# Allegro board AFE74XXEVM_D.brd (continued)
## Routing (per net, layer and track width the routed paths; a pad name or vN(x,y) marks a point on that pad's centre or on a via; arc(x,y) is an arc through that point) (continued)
VDDA_1.0V: length 1.6
  L4_SIG w0.203: 53.75,66.95 53.6,67.1 v1(53.55,67.1) 53.54,67.1 53.26,66.83 ; 53.77,60.1 53.58,59.9 v1(53.55,59.9) 53.51,59.9 53.26,60.15
  BOTTOM w0.102: 54.69,59.28 54.69,59.33 54.58,59.44 54.53,59.44
  vias: v1(54.83,47.46) v1(54.83,46.58) v1(54.83,45.69) v1(55.63,48.33) v1(55.85,47.46) v1(55.85,46.58) v1(55.85,45.69) v1(104.65,17.02) v1(104.65,16) v1(104.65,14.99) v1(104.65,13.84) v1(105.92,17.02) v1(105.92,16) v1(105.92,14.99) v1(105.92,13.84)
VDDA_1.8V: length 0.2
  BOTTOM w0.305: v1(51.15,66.3) 51.06,66.3 C79.1 ; v1(51.15,61.5) 51.14,61.49 C80.1
  vias: v1(31.24,67.7) v1(31.17,54.86) v1(31.91,67.7) v1(31.85,54.84) v1(33.91,78.96) v1(34.47,78.6) v1(36,44.61) v1(36.53,44.93) v1(38.03,71.19) v1(38.03,68.38) v1(37.95,58.45) v1(37.97,55.78) v1(37.96,52.88) v1(38.1,73.91) v1(39.98,65.13) v1(40.11,51.1) v1(40.21,76.09) v1(41.45,48.74) v1(41.61,78.47) v1(51.15,65.5) v1(51.15,60.7) v1(86.28,32.56) v1(86.28,31.55) v1(87.3,32.56) v1(87.3,31.55) v1(88.32,32.56) v1(88.32,31.55) v1(89.33,32.56) v1(89.33,31.55) v3(37.54,55.12) v3(37.57,59.09) v3(37.67,71.76) v3(37.67,67.8) v3(38.33,59.09) v3(38.25,55.12) v3(38.42,71.78) v3(38.39,67.81) v3(39.5,51.49) v3(39.58,75.77) v3(40.11,51.84) v3(40.24,75.39) v3(41.45,48.01) v3(41.6,79.21) v3(42.06,48.36) v3(42.26,78.83)
VDDA_SERDES_1.0V: length 1.1
  L8_PWR_SIG w0.102: 61.98,58.52 61.82,58.68 61.39,58.68 61.31,58.6 61.14,58.6
  BOTTOM w0.254: v1(63.15,68.7) C115.1 ; C116.1 v1(63.15,58.3)
  vias: v1(62.35,68.7) v1(62.35,58.3) v1(74.93,75.36) v1(136.58,36.45) v1(136.6,35.56) v1(137.59,36.47) v1(137.62,35.59) v1(138.71,36.47) v1(138.73,35.59) v1(139.6,36.47) v1(139.62,35.59)
VDDCLK_1.0V: length 1.8
  BOTTOM w0.305: 52.75,61.43 C109.1 ; 52.75,61.43 v1(52.75,61.5) ; 52.75,61.43 v1(52.75,60.7) ; v1(51.95,63.1) 51.94,63.09 C431.1 ; v1(52.75,66.3) v1(52.75,65.5)
  vias: v1(61.76,45.19) v1(104.65,12.19) v1(104.65,11.18) v1(104.65,10.16) v1(104.65,9.14) v1(105.79,12.19) v1(105.79,11.18) v1(105.79,10.16) v1(105.79,9.14)
VDDE: length 5.1
  L8_PWR_SIG w0.305: v1(54.35,64.7) v1(54.35,65.5) v1(54.35,66.3) v1(54.35,67.1) ; v1(54.35,62.3) v1(54.35,61.5) v1(54.35,60.7) v1(54.35,59.9)
  BOTTOM w0.305: C123.1 54.43,67.18 v1(54.35,67.1)
  vias: v1(68.11,50.3) v1(133.63,15.9) v1(133.63,13.84) v1(133.65,14.96) v1(134.75,15.88) v1(134.77,14.94) v1(134.75,13.82) v3(62.36,55.24) v3(63.41,53.06) v3(63.9,53.54)
VDDGPIO_1.8V: length 309.8
  TOP w0.508: J9.60 J9.63
  L3_PWR w0.102: 51.66,58.47 51.52,58.47 51.31,58.68 50.99,58.68 50.73,58.42 50.73,58.22
  L3_PWR w0.381: 51.74,58.12 51.92,58.3 v1(51.95,58.3)
  L3_PWR w0.508: 165.07,110.39 165.07,101.36 165.05,101.34 165.05,95.31 165.07,95.28 165.07,85.5 180.92,69.65 180.92,64.69 181.15,64.47 181.15,50.33 181.76,49.72 181.76,48.91 180.96,48.11 180.96,47.39 181.48,46.87 181.48,46.35 180.59,45.46 180.59,44.59 180.9,44.29 180.9,43.57 179.91,42.58 179.91,42.05 180.94,41.02 180.94,38.9 180.2,38.16 180.2,36.26 180.57,35.89 180.57,33.48 179.15,32.05 173.66,32.05 172.54,30.94 169.32,30.94 167.97,32.28 163.37,32.28 157.23,26.14 157.23,19.41 152.68,14.86 144.25,14.86 142.21,12.83 138.33,12.83 133.07,7.56 132.32,7.56 131.59,6.84 131.59,6.09 129.01,3.51 124.74,3.51 121.79,6.45 116.97,6.45 113.85,3.33 99.77,3.33 92.81,10.29 92.81,16.23 93.45,16.87 93.45,20.94 93.32,21.06 93.32,22.96 93.45,23.08 93.45,25.04 93.34,25.14 93.34,27.38 93.52,27.56 v1(93.52,31.55) ; 165.07,110.39 J9.60 ; 165.07,110.39 J9.57 162.41,111.76 156.77,111.76 155.35,113.18 155.35,118.87 154.05,120.17 JP7.2 ; JP7.2 154.99,122.38 v1(155.88,122.38) 155.88,122.33 156.79,121.41 159.13,121.41 JP8.2 ; JP7.2 152.3,121.56 149.45,121.56 v1(148.64,122.38) 147.75,122.38 JP6.2 144.86,121.36 142.44,121.36 141.55,122.25 v1(141.55,122.28) 140.74,122.28 JP5.2 137.9,121.51 134.98,121.51 v1(134.16,122.33) 133.45,122.33 JP4.2 130.38,121.23 127.79,121.23 126.87,122.15 v1(126.87,122.2) 126.21,122.2 JP3.2 123.29,121.51 120.5,121.51 v1(119.66,122.35) ; v1(112.55,122.35) 113.59,121.31 115.85,121.31 117.86,123.32 118.82,122.35 v1(119.66,122.35) ; v1(119.41,118.01) 119.66,118.26 v1(119.66,122.35)
  vias: v1(49.99,54.89) v1(90.47,32.56) v1(90.47,31.55) v1(91.49,32.56) v1(91.49,31.55) v1(92.51,32.56) v1(92.51,31.55) v1(93.52,32.56)
VDDL1_1.0V: length 4
  L8_PWR_SIG w0.102: 52.59,60.32 52.68,60.32 ; 52.59,60.32 52.59,60.28 52.37,60.06 52.37,59.67 52.55,59.49 ; 52.59,60.32 52.37,60.54 52.37,60.86 52.63,61.12 52.63,61.14
  BOTTOM w0.305: v1(53.55,61.5) v1(53.55,60.7) ; C106.1 53.39,66.46 v1(53.55,66.3) v1(53.55,65.5)
  vias: v1(55.96,54.33) v1(107.04,22.61) v1(107.04,21.59) v1(107.04,20.57) v1(107.04,19.56) v1(108.31,22.61) v1(108.31,21.59) v1(108.31,20.57) v1(108.31,19.56)
VDDL2_1.0V: length 3.9
  L8_PWR_SIG w0.102: 50.51,67.52 50.19,67.52 49.97,67.74 49.97,68.14 49.91,68.2 ; 50.8,67.36 50.8,67.29 50.77,67.26 50.77,66.94 50.99,66.72 51.33,66.72 51.38,66.78 ; 51.77,68.28 52.11,68.28 52.33,68.06 52.33,67.74 52.32,67.73 52.32,67.67
  BOTTOM w0.305: C103.1 51.79,61.66 v1(51.95,61.5) ; C102.1 51.77,65.32 v1(51.95,65.5)
  vias: v1(41.85,73.38) v1(51.95,66.3) v1(51.95,60.7) v1(104.39,7.37) v1(104.39,6.35) v1(104.39,5.33) v1(104.39,4.32) v1(105.66,7.37) v1(105.66,6.35) v1(105.66,5.33) v1(105.66,4.32)
VDDPLL_1.0V: length 5.6
  L8_PWR_SIG w0.102: 49.28,65.15 49.35,65.08 49.71,65.08 49.93,64.86 49.93,64.41 ; 50.73,63.71 50.73,64.06 50.51,64.28 50.19,64.28 50.15,64.24 50.14,64.24
  L8_PWR_SIG w0.127: 38.4,58.57 38.4,58.27 38.02,57.89 37.85,57.89 ; 43.51,62.81 43.65,62.67 43.65,62.66 43.91,62.4 44.81,62.4 45.21,62.79
  BOTTOM w0.305: v1(51.15,63.1) 50.96,62.91 C92.1
  vias: v1(45.29,65.05) v1(94.74,23.75) v1(94.74,22.61) v1(94.74,21.59) v1(94.74,20.57) v1(96.01,23.75) v1(96.01,22.61) v1(96.01,21.59) v1(96.01,20.57)
VDDPLL_1.8V: length 0.9
  L3_PWR w0.102: 50.72,62.2 50.72,62.05 50.55,61.88 50.34,61.88
  BOTTOM w0.305: v1(51.15,63.9) 50.98,64.07 C94.1
  vias: v1(43.61,48.87) v1(77.65,32.56) v1(77.65,31.55) v1(78.66,32.56) v1(78.66,31.55) v1(79.81,32.56) v1(79.81,31.55) v1(80.82,32.56) v1(80.82,31.55)
VDDR_SERDES_1.5V: length 4.1
  L8_PWR_SIG w0.102: 64.31,60.93 64.25,60.93 64.11,61.08 63.79,61.08 63.65,60.93 63.5,60.93 63.49,60.92 ; 62.03,60.93 62.05,60.93 62.19,61.08 62.51,61.08 62.77,60.82 62.77,60.86 62.99,61.08 63.33,61.08 63.49,60.92 ; 63.58,60.83 63.49,60.92 ; 64.33,60.83 64.59,61.08 64.91,61.08 65.05,60.93 65.15,60.93
  L8_PWR_SIG w0.127: 65.18,60.93 65.15,60.93
  BOTTOM w0.305: v1(63.15,59.9) 63.24,59.9 C112.1 ; v1(63.15,67.1) 63.24,67.1 C113.1
  vias: v1(62.35,67.1) v1(62.35,59.9) v1(68.88,56.64) v1(122.89,35.2) v1(122.89,34.19) v1(123.98,35.23) v1(123.98,34.21) v1(125.04,35.23) v1(125.04,34.21) v1(126.09,35.26) v1(126.09,34.24)
VDDT_SERDES_1.0V: length 0.2
  BOTTOM w0.305: C118.1 63.23,65.5 v1(63.15,65.5) ; C119.1 v1(63.15,61.5)
  vias: v1(62.35,65.5) v1(62.35,61.5) v1(131.65,36.5) v1(131.65,35.56) v1(132.69,36.5) v1(132.69,35.56) v1(133.78,36.5) v1(133.78,35.56) v1(134.77,36.5) v1(134.77,35.56)
VDDTX_1.0V: length 1.3
  L3_PWR w0.102: 56.11,55.52 55.79,55.52 55.57,55.74 55.57,56.04 55.5,56.11
  BOTTOM w0.305: C100.1 53.64,62.39 v1(53.55,62.3)
  vias: v1(58.37,55.27) v1(62.76,51.82) v1(105.28,31.37) v1(105.28,30.35) v1(105.28,29.34) v1(105.28,28.32) v1(106.43,31.37) v1(106.43,30.35) v1(106.43,29.34) v1(106.43,28.32)
VDDTX_1.8V: length 4.9
  L8_PWR_SIG w0.102: 51.56,61.57 51.53,61.54 51.53,61.34 51.3,61.11 51.05,61.11 ; 51.64,62.81 51.64,62.87 51.57,62.94 51.57,63.26 51.79,63.48 51.89,63.48 ; 51.87,61.88 52.07,61.88 52.33,62.14 52.33,62.31 ; 50.83,62.03 50.83,62.09 50.77,62.14 50.77,62.46 50.99,62.68 51.39,62.68 51.54,62.53 ; 50.31,60.32 50.51,60.32 50.73,60.54 50.73,60.74 50.77,60.78 50.77,60.83
  BOTTOM w0.305: v1(52.75,63.1) 52.74,63.09 C98.1
  vias: v1(43.91,57.53) v1(82.09,32.56) v1(82.09,31.55) v1(83.11,32.56) v1(83.11,31.55) v1(84.12,32.56) v1(84.12,31.55) v1(85.14,32.56) v1(85.14,31.55)
VDDVCO_1.8V: length 5.7
  L8_PWR_SIG w0.102: 51.44,65.15 51.53,65.25 51.53,65.66 51.31,65.88 50.96,65.88 50.93,65.91 ; 50.19,66.7 50.21,66.68 50.51,66.68 50.73,66.46 50.73,66.14 50.69,66.1 ; 49.28,67.44 49.35,67.44 49.39,67.48 49.71,67.48 49.93,67.26 49.93,66.94
  L8_PWR_SIG w0.127: 37.41,68.66 37.68,68.66 37.85,68.83 38.49,68.83 38.66,68.66
  BOTTOM w0.254: v1(51.95,63.9) 52.1,64.05 C96.1 52.1,64.55 v1(51.95,64.7)
  vias: v1(46.84,68.1) v1(95.05,32.56) v1(95.05,31.42) v1(96.06,32.56) v1(96.06,31.42) v1(97.08,32.56) v1(97.08,31.42) v1(98.09,32.56) v1(98.09,31.42)
VEE: length 0.3
  BOTTOM w0.305: C64.1 51.09,67.9 v1(51.15,67.9) ; v1(51.95,67.9) 52.04,67.9 C62.1
  vias: v1(32.16,36.36) v1(49.81,72.42) v1(51.15,59.1) v1(51.15,58.3) v1(51.95,68.7) v1(51.95,59.1) v1(79.43,6.32) v1(79.4,5.36) v1(80.54,6.32) v1(80.52,5.36) v1(81.74,5.36) v1(81.76,6.32) v1(82.88,6.3) v1(82.85,5.33) v3(49.02,68.68) v3(49.02,67.94) v3(48.97,59.05) v3(48.97,58.34)
3P3V_FMC:
  vias: v2(211.46,43.81) v2(211.46,41.27) v2(211.46,38.73) v2(212.73,40)
3P3VAUX:
  vias: v1(187.2,20.17) v1(187.87,20.17) v1(188.52,20.17) v2(211.46,48.89)
A_IN1: length 15.1
  TOP w0.381: J14.1 29.09,15.62 arc(30.5,17.37) 32.41,18.56 R50.2 38.83,21.17 R54.1
A_IN2: length 15.3
  TOP w0.381: R332.1 R330.2 43.09,12.38 arc(42.51,10.18) 41.56,8.11 J15.1
ADC_ALT_SYNC_N: length 167.1
  L6_SIG w0.102: v2(206.38,48.89) 205.94,49.33 203.52,49.33 203.5,49.31 203.48,49.31 ; v1(57.55,65.5) 57.14,65.09 56.56,65.09 56.34,64.87 56.34,64.38 56.24,64.28 55.79,64.28 55.57,64.06 55.57,63.32 55.53,63.28 55.53,55.36
  L6_SIG w0.127: 55.53,55.36 55.53,55.28 55.75,55.06 56.35,55.06 57.95,53.45 58.67,53.45 63.35,48.77 63.35,48.54 63.93,47.96 66.93,47.96 67.84,48.87 100.23,48.87 101.02,48.08 201.73,48.08 202.96,49.31 203.48,49.31
ADC_ALT_SYNC_P: length 167.1
  L6_SIG w0.102: v1(56.75,65.5) 56.75,65.54 57.12,65.91 57.68,65.91 57.68,65.91 57.72,65.91 57.96,65.67 57.96,65.63 57.96,65.63 57.96,64.57 57.71,64.32 57.41,64.32 57.17,64.08 57.17,63.78 56.91,63.52 56.61,63.52 56.36,63.27 56.36,55.65 56.65,55.36 ; v2(206.38,50.16) 205.94,49.73 203.67,49.73 203.66,49.75 203.48,49.75
  L6_SIG w0.127: 203.48,49.75 202.78,49.75 201.55,48.51 101.2,48.51 100.41,49.3 67.66,49.3 66.75,48.39 64.11,48.39 63.78,48.72 63.78,48.95 58.85,53.88 58.13,53.88 56.65,55.36
ADC_SYNC_N: length 158.6
  L6_SIG w0.102: v2(207.65,73.02) 207.21,73.46 206.97,73.46 205.7,72.19 203.48,72.19 ; v1(57.55,61.5) 57.97,61.92 58.51,61.92 58.73,62.14 58.73,62.53 58.92,62.72 59.31,62.72 59.57,62.98 59.57,65.66 59.79,65.88 59.79,65.89 64.88,65.89 65.08,66.09 65.15,66.09
  L6_SIG w0.127: 65.15,66.09 65.58,66.09 65.69,65.98 65.69,65.89 65.8,65.78 65.96,65.78 66.07,65.89 66.07,65.98 66.18,66.09 66.34,66.09 66.45,65.98 66.45,65.89 66.56,65.78 66.72,65.78 66.83,65.89 66.83,65.98 66.94,66.09 67.1,66.09 67.21,65.98 67.21,65.89 67.32,65.78 67.48,65.78 67.59,65.89 67.59,65.98 67.7,66.09 67.86,66.09 67.97,65.98 67.97,65.89 68.08,65.78 68.24,65.78 68.35,65.89 68.35,65.98 68.47,66.09 73.05,66.09 73.2,65.94 104.52,65.94 110.67,72.09 201.37,72.09 201.47,72.19 203.48,72.19
ADC_SYNC_P: length 158.6
  L6_SIG w0.102: v1(56.75,61.5) 57.13,61.88 57.13,62.5 57.35,62.72 57.76,62.72 57.97,62.93 57.97,63.26 58.19,63.48 58.51,63.48 58.77,63.74 58.77,66.46 58.99,66.68 64.91,66.68 65.07,66.52 65.15,66.52 ; 203.48,72.62 203.49,72.62 203.5,72.61 203.65,72.61 203.67,72.59 205.51,72.59 206.78,73.86 207.21,73.86 v2(207.65,74.3)
  L6_SIG w0.127: 203.48,72.62 201.29,72.62 201.19,72.52 110.49,72.52 104.34,66.37 73.38,66.37 73.23,66.52 65.15,66.52
AIN1: length 3.9
  TOP w0.381: C132.2 L7.2 40.5,27.39 T4.3
AIN1M: length 10
  TOP w0.203: C136.1 46.99,48.03 arc(47.04,48.26) 47.16,48.45 47.46,48.77 48.78,50 arc(49.2,50.41) 49.59,50.86 49.77,51.07 arc(50.83,52.53) 51.73,54.08 52.21,55.02 52.21,55.02 52.31,55.22 arc(52.35,55.29) 52.39,55.36 arc(52.39,55.36) 52.4,55.36 arc(52.57,55.63) 52.75,55.89 U1.A16
AIN1P: length 10
  TOP w0.203: U1.A17 51.95,55.9 arc(52.08,55.74) 52.09,55.53 51.83,55.01 51.44,54.23 arc(50.56,52.71) 49.51,51.28 49.34,51.07 arc(48.96,50.64) 48.56,50.24 46.98,48.79 arc(46.85,48.64) 46.75,48.47 46.63,48.19 arc(46.56,48.1) 46.45,48.07 C131.1
AIN2: length 3.9
  TOP w0.381: T6.3 L51.2 C471.2
AIN2M: length 10
  TOP w0.203: U1.A13 55.04,55.84 55,55.71 54.96,55.54 54.96,55.54 54.93,55.41 54.93,55.41 54.93,55.37 54.92,55.36 54.92,55.36 54.59,53.82 54.59,53.81 54.55,53.5 arc(54.2,51.45) 53.58,49.47 52.44,46.59 C475.1
AIN2P: length 10
  TOP w0.203: C474.1 52.12,46.67 53.27,49.59 arc(53.88,51.53) 54.23,53.54 54.26,53.87 54.27,53.89 54.6,55.43 54.6,55.54 arc(54.58,55.64) 54.52,55.73 U1.A14
ALARM_TX1: length 1.6
  BOTTOM w0.127: J7.1 125.55,94.26 Q3.1
ALARM_TX2: length 1.6
  BOTTOM w0.127: Q4.1 128.09,94.26 J7.4
ALARMTX1: length 124.1
  L4_SIG w0.102: 49.15,58.71 51.28,58.71 51.56,58.43 51.56,57.89 v1(51.95,57.5)
  L4_SIG w0.127: J7.2 123.62,98.32 122.68,97.38 v1(120.68,97.38) ; v1(50.32,97) 47.3,93.99 47.3,88.56 46.19,87.45 46.19,85.05 48.42,82.83 48.42,78.82 48.07,78.47 48.07,76.6 48.52,76.15 48.52,75.78 48.12,75.38 48.12,67.93 48.4,67.65 48.4,62.11 47.76,61.47 47.76,60.41 48.63,59.54 48.63,58.91 48.83,58.71 49.15,58.71
  L8_PWR_SIG w0.127: v1(120.68,97.38) 120.47,97.18 118.41,97.18 117.81,97.79 108.64,97.79 107.67,96.82 105.84,96.82 105.59,97.08 98.18,97.08 97.67,97.59 90.12,97.59 89.84,97.3 83.31,97.3 83.1,97.1 67.83,97.1 67.6,97.32 60.33,97.32 59.39,96.39 57.69,96.39 56.69,97.38 50.7,97.38 v1(50.32,97)
ALARMTX2: length 111
  L4_SIG w0.102: v1(51.95,69.5) 51.91,69.5 51.56,69.85 51.56,71.5
  L4_SIG w0.127: 51.56,71.5 51.56,71.53 51.95,71.92 51.95,72.94 51.66,73.23 51.66,78.97 52.96,80.27 52.96,80.3 53.27,80.61 53.27,87.22 51.78,88.72 51.78,93.4 55.35,96.97 v1(55.35,98.48)
  L6_SIG w0.127: v1(120.21,98.84) 120.21,97.22 120.5,96.93 126.7,96.93 J7.5
  L8_PWR_SIG w0.127: v1(55.35,98.48) 56.75,98.48 57.79,99.52 60.88,99.52 61.8,98.6 67.37,98.6 67.5,98.73 67.51,98.73 67.8,99.02 68.34,99.57 68.74,99.57 69.36,98.95 72.92,98.95 73.38,98.48 89.09,98.48 89.61,99.01 98.17,99.01 98.78,98.4 105.56,98.4 107.68,100.52 113.6,100.52 114.35,99.77 119.28,99.77 v1(120.21,98.84)
B_IN1: length 19
  TOP w0.381: J16.1 59.85,5 arc(60.05,7.02) 60.62,8.96 R72.2 R76.1
B_IN2: length 20
  TOP w0.381: J17.1 73.81,4.27 arc(73.67,6.48) 73.27,8.66 R335.2 R337.1
BIN1: length 4
  TOP w0.381: C137.2 L8.2 63.11,25.55 62.35,28.4 T8.3
BIN1M: length 9.7
  TOP w0.203: C145.1 58.33,46.51 arc(58.19,46.57) 58.13,46.7 57.38,55.35 57.38,55.42 57.37,55.5 arc(57.41,55.72) U1.A10
BIN1P: length 9.7
  TOP w0.203: C144.1 57.81,46.57 57.05,55.32 57.05,55.39 57.05,55.42 57.04,55.42 arc(56.95,55.7) 56.75,55.9 U1.A11
BIN2: length 4
  TOP w0.381: T10.3 67.88,29.88 68.64,27.04 L55.2 C479.2
BIN2M: length 9.7
  TOP w0.203: C483.1 63.73,48.05 arc(63.68,48.2) 63.64,48.35 63.49,48.89 63.22,49.51 63.21,49.53 arc(62.84,49.99) 62.39,50.38 61.07,51.34 arc(60.5,51.9) 60.1,52.59 arc(59.98,53.04) 59.91,53.51 59.79,55.36 59.79,55.37 59.79,55.63 59.75,55.66 arc(59.75,55.67) 59.75,55.68 arc(59.79,55.82) 59.91,55.89 U1.A7
BIN2P: length 9.7
  TOP w0.203: C482.1 63.37,47.87 63.37,48.04 63.32,48.27 63.18,48.78 62.93,49.35 62.93,49.35 arc(62.6,49.77) 62.2,50.12 60.88,51.07 arc(60.23,51.7) 59.79,52.47 59.79,52.47 arc(59.65,52.97) 59.58,53.48 59.46,55.33 59.46,55.36 59.42,55.62 arc(59.42,55.62) 59.42,55.63 arc(59.42,55.64) 59.42,55.66 arc(59.34,55.81) 59.19,55.89 U1.A8
BOOT: length 1.3
  TOP w0.305: R235.2 154.21,13.2 U16.4
C_IN1: length 15.4
  TOP w0.381: R94.1 R96.2 31.16,110.86 arc(30.37,111.42) 29.77,112.19 J18.1
C_IN2: length 15.5
  TOP w0.381: R342.1 R340.2 43.9,115.52 arc(43.24,117.61) 42.29,119.57 J19.1
CAR_SYSREF_M: length 3
  BOTTOM w0.203: U3.4 104.59,85.91 104.67,85.83 104.67,85.4 104.32,85.05 104.32,84.28 R162.1 104.19,84.1 R158.1
CAR_SYSREF_P: length 3.1
  BOTTOM w0.203: U3.3 105.09,85.89 105,85.8 105,85.27 104.65,84.91 104.65,84.3 R163.1 104.83,83.52 R156.1
CAR_SYSREFM: length 108.7
  BOTTOM w0.102: 203.48,77.32 203.5,77.32 203.56,77.37 207.54,77.37 207.65,77.27 J32.G10
  BOTTOM w0.203: R158.2 104.33,82.74 104.33,81.18 107.1,78.41 144.3,78.41 144.75,78.87 146.66,78.87 147.12,78.41 153.9,78.41 154.38,78.89 156.24,78.89 156.72,78.41 159.33,78.41 159.72,78.79 161.65,78.79 162.03,78.41 164.24,78.41 164.77,78.94 165.94,78.94 166.47,78.41 201.44,78.41 202.53,77.32 203.48,77.32
CAR_SYSREFP: length 108.7
  BOTTOM w0.102: 203.48,77.65 203.5,77.65 203.56,77.6 207.56,77.6 207.65,77.69 J32.G9
  BOTTOM w0.203: R156.2 104.66,82.74 104.66,81.32 105.02,80.96 105.27,80.96 105.36,81.05 105.62,81.05 105.79,80.87 105.79,80.62 105.7,80.53 105.7,80.28 107.24,78.74 144.16,78.74 144.62,79.2 146.8,79.2 147.25,78.74 153.76,78.74 154.24,79.22 156.37,79.22 156.85,78.74 159.2,78.74 159.58,79.12 161.78,79.12 162.16,78.74 164.1,78.74 164.63,79.27 166.08,79.27 166.61,78.74 201.57,78.74 202.67,77.65 203.48,77.65
CIN1: length 3.9
  TOP w0.381: C155.2 L12.2 T12.3
CIN1M: length 10
  TOP w0.203: U1.Y16 52.61,71.2 52.56,71.5 52.46,71.79 52.44,71.85 47.16,78.86 C147.1
CIN1P: length 10
  TOP w0.203: U1.Y17 52.18,71.33 52.18,71.6 52.14,71.69 46.61,79.04 C146.1
CIN2: length 3.9
  TOP w0.381: C487.2 L59.2 T14.3
CIN2M: length 10
  TOP w0.203: C491.1 52.57,80.51 54.96,71.58 54.96,71.58 54.99,71.5 U1.Y13
CIN2P: length 10
  TOP w0.203: U1.Y14 54.54,71.23 54.6,71.5 54.62,71.58 52.26,80.4 C490.1
CLK0_M2C_N: length 143.5
  L6_SIG w0.102: v2(206.38,83.19) 206.38,83.5 206.49,83.61 206.8,83.61 207.13,83.94 207.21,84.02 207.21,88.65
  L6_SIG w0.127: 207.21,88.65 207.21,88.73 207.19,88.75 207.19,88.82 206.2,89.81 205.84,89.81 193.11,89.81 192.58,89.28 191.34,89.28 190.8,89.81 180.65,89.81 175.18,95.28 175.18,96.78 173.38,98.58 170.54,98.58 169.33,99.78 114.79,99.78 112.62,97.61 107.82,97.61 105.97,95.76 105.97,87.66 104.52,86.21 102.31,86.21 101.72,85.61 100.9,85.61 99.84,86.67 93.92,86.67 92.48,88.11 92.48,89.01 92.58,89.11 92.58,89.42 92.48,89.52 92.48,91.75 92.9,92.17 93.48,92.17 v1(93.59,92.06)
CLK0_M2C_P: length 143.4
  L6_SIG w0.102: v2(206.38,84.45) 206.38,84.12 206.49,84.01 206.63,84.01 206.72,84.11 206.81,84.19 206.81,88.56 206.75,88.61 206.75,88.65
  L6_SIG w0.127: 206.75,88.65 206.02,89.38 193.29,89.38 192.76,88.85 191.16,88.85 190.63,89.38 180.47,89.38 174.75,95.1 174.75,96.6 173.2,98.15 170.36,98.15 169.15,99.35 114.97,99.35 112.8,97.18 108,97.18 106.4,95.58 106.4,87.48 104.7,85.78 102.49,85.78 101.9,85.18 100.72,85.18 99.66,86.24 93.74,86.24 92.05,87.93 92.05,91.97 92.68,92.6 93.53,92.6 v1(93.59,92.67)
CLK1_M2C_N: length 143.3
  L6_SIG w0.102: 208.5,88.65 208.5,88.63 208.48,88.62 208.48,87.82 208.73,87.58 208.73,86.5 208.39,86.16 207.75,86.16 207.65,86.06 v2(207.65,85.72)
  L6_SIG w0.127: 208.5,88.65 208.5,90.08 206.12,92.46 200.99,92.46 199.14,94.31 199.14,99.42 197.33,101.22 189.89,101.22 189.6,100.93 188.56,100.93 187.55,101.93 186.16,101.93 185.39,101.17 185.39,99.7 185.06,99.36 183.97,99.36 182.63,100.71 177.7,100.71 176.81,99.82 171.88,99.82 168.85,102.86 141,102.86 140.44,102.3 128.21,102.3 128.12,102.39 116.45,102.39 116.11,102.72 115.02,102.72 114.68,102.39 100.61,102.39 99.8,101.57 97.03,101.57 94.77,99.31 92.56,99.31 91.74,98.5 91.74,97.46 92.11,97.09 92.11,96.08 91.82,95.79 91.82,94.64 92.43,94.03 93.73,94.03 93.84,93.93 v1(94.26,93.93)
CLK1_M2C_P: length 143.3
  L6_SIG w0.102: v2(207.65,86.99) 207.65,86.66 207.75,86.56 208.22,86.56 208.32,86.66 208.32,87.41 208.08,87.66 208.08,88.45 208.06,88.47 208.06,88.65
  L6_SIG w0.127: v1(94.26,94.56) 93.84,94.56 93.73,94.46 92.61,94.46 92.25,94.82 92.25,95.61 92.54,95.9 92.54,96.17 92.66,96.28 92.88,96.28 92.99,96.39 92.99,96.55 92.88,96.66 92.66,96.66 92.54,96.77 92.54,97.27 92.18,97.64 92.18,98.32 92.74,98.88 92.89,98.88 93,98.77 93,98.56 93.11,98.45 93.27,98.45 93.38,98.56 93.38,98.77 93.49,98.88 94.95,98.88 97.21,101.14 99.97,101.14 100.79,101.96 114.86,101.96 115.19,102.29 115.94,102.29 116.27,101.96 127.94,101.96 128.03,101.87 140.62,101.87 141.18,102.43 168.67,102.43 171.7,99.39 176.99,99.39 177.88,100.28 182.45,100.28 183.79,98.93 185.24,98.93 185.83,99.52 185.83,100.99 186.33,101.5 187.38,101.5 188.38,100.5 189.78,100.5 190.07,100.79 197.15,100.79 198.7,99.24 198.7,98.79 198.59,98.68 198.33,98.68 198.22,98.57 198.22,98.41 198.33,98.3 198.59,98.3 198.7,98.19 198.7,94.13 200.81,92.02 205.94,92.02 206.15,91.81 206.15,91.66 206.03,91.53 206.03,91.38 206.14,91.27 206.3,91.27 206.42,91.39 206.58,91.39 208.06,89.9 208.06,89.75 207.95,89.63 207.86,89.63 207.75,89.52 207.75,89.36 207.86,89.25 207.95,89.25 208.06,89.14 208.06,88.65
CLK-IN: length 3.7
  BOTTOM w0.381: R161.2 97.96,108.01 R165.1 97.93,106.02 T24.6 R159.1
CLK_LAO_0M: length 110.6
  L6_SIG w0.102: 203.48,81.08 203.49,81.08 207.42,81.08 207.65,80.85 v2(207.65,80.64)
  L6_SIG w0.127: 203.48,81.08 203.36,81.2 176.69,81.2 174.99,82.91 173.17,82.91 171.34,81.08 169.15,81.08 167.32,82.91 165.49,82.91 163.67,81.08 161.48,81.08 159.65,82.91 157.82,82.91 156,81.08 153.81,81.08 151.98,82.91 150.15,82.91 148.32,81.08 146.14,81.08 144.31,82.91 142.48,82.91 140.65,81.08 138.47,81.08 136.64,82.91 134.81,82.91 132.98,81.08 130.8,81.08 128.97,82.91 127.14,82.91 125.39,81.15 123.7,81.15 117.68,87.17 112.6,87.17 112.09,87.68 110.72,87.68 v1(110.62,87.58)
CLK_LAO_0P: length 110.7
  L6_SIG w0.102: 203.48,81.64 203.5,81.64 203.66,81.48 207.47,81.48 207.65,81.66 v2(207.65,81.91)
  L6_SIG w0.127: v1(110.62,88.19) 110.69,88.11 112.27,88.11 112.78,87.6 117.86,87.6 123.88,81.58 125.21,81.58 126.96,83.34 129.15,83.34 130.98,81.51 132.8,81.51 134.63,83.34 136.82,83.34 138.65,81.51 140.47,81.51 142.3,83.34 144.49,83.34 146.32,81.51 148.15,81.51 149.97,83.34 152.16,83.34 153.99,81.51 155.82,81.51 157.64,83.34 159.83,83.34 161.66,81.51 163.49,81.51 165.32,83.34 167.5,83.34 169.33,81.51 171.16,81.51 172.99,83.34 175.17,83.34 176.87,81.64 203.48,81.64
CLK_N: length 13.1
  L6_SIG w0.102: 49.15,64.05 49.33,64.05 49.36,64.02 49.43,64.02 49.75,63.7 50.15,63.7 v1(50.35,63.9)
  L6_SIG w0.127: v1(39.24,62.81) 39.51,62.55 40.16,62.55 41.66,64.05 49.15,64.05
  BOTTOM w0.305: R295.1 50.23,63.78 v1(50.35,63.9)
  BOTTOM w0.381: R323.1 39.17,62.74 v1(39.24,62.81) L2.1
CLK_P: length 13.1
  L6_SIG w0.102: 49.15,63.61 49.26,63.61 49.58,63.3 50.15,63.3 v1(50.35,63.1)
  L6_SIG w0.127: 49.15,63.61 41.84,63.61 40.34,62.12 39.43,62.12 v1(39.24,61.93)
  BOTTOM w0.305: v1(50.35,63.1) 50.28,63.17 R295.2
  BOTTOM w0.381: R322.1 39.17,62.03 L1.1 v1(39.24,61.93)
CLKIN1_N: length 1.4
  BOTTOM w0.381: L43.2 99.66,98.41 99.66,98.97 C230.2 99.59,99.03 C231.2
CLKIN1_P: length 0.8
  BOTTOM w0.381: L44.2 98.98,98.48 C227.2
CLKIN1N: length 2.1
  BOTTOM w0.203: L43.1 99.48,97.04 99.48,96.76 C239.2 99.54,96.55 99.54,95.48 U3.35
CLKIN1P: length 2.1
  BOTTOM w0.203: L44.1 99.09,97.04 99.09,96.76 C238.2 99.14,96.44 99.14,95.49 U3.34
CLKINN: length 2.9
  BOTTOM w0.381: C231.1 99.59,100.86 R166.2 100.43,101.7 T24.3
CLKINP: length 4.4
  BOTTOM w0.381: C227.1 98.96,99.67 R157.1 98.96,100.84 R166.1 97.89,101.9 T24.1 R159.2
CLKLA_0M: length 3.2
  BOTTOM w0.203: U3.63 107.74,87.6 107.82,87.69 108.5,87.69 108.53,87.72 109.21,87.72 R192.1 109.98,87.55 R191.1
CLKLA_0P: length 3.2
  BOTTOM w0.203: U3.62 107.74,88.1 107.82,88.02 108.37,88.02 108.4,88.05 109.21,88.05 R190.1 109.98,88.21 R189.1
CLKN: length 94.7
  L6_SIG w0.127: v1(96.78,82.4) 96.57,82.4 96.27,82.1 96.27,80.59 95.67,79.98 93.37,79.98 93.07,79.68 93.07,75.21 92.15,74.3 84.87,74.3 80.47,78.69 79.72,78.69 79.22,79.19 79.22,83.96 78.95,84.23 78.58,84.23 78.37,84.02 73.78,84.02 73.49,83.73 73.49,81.95 71.51,79.96 68.42,79.96 67.16,81.23 67.16,82.01 65.66,83.51 63.9,83.51 62.46,82.07 59.65,82.07 58.41,80.83 56.78,80.83 54.82,78.87 52.74,78.87 51.83,77.97 51.83,77.31 52.3,76.84 52.3,74.9 51.49,74.09 48.56,74.09 46.41,71.94 44.95,71.94 42.62,69.6 42.62,67.34 41.71,66.43 38.87,66.43 38.39,65.95 38.39,65.79 38.49,65.7 38.49,65.54 38.38,65.43 38.22,65.43 38.12,65.52 37.96,65.52 37.72,65.28 37.72,63.84 37.83,63.73 38.04,63.73 38.15,63.61 38.15,63.46 38.04,63.34 37.83,63.34 37.72,63.23 37.72,62.92 38.03,62.61 38.3,62.61 39.27,63.58 v1(39.27,63.83)
CLKP: length 94.7
  L6_SIG w0.127: v1(39.27,60.91) 39.27,61.21 38.3,62.18 37.85,62.18 37.29,62.74 37.29,65.46 38.69,66.86 41.53,66.86 42.19,67.52 42.19,69.78 44.78,72.37 46.23,72.37 48.39,74.52 51.31,74.52 51.87,75.08 51.87,76.66 51.4,77.13 51.4,78.15 52.56,79.31 54.64,79.31 56.6,81.26 58.23,81.26 59.47,82.5 62.28,82.5 63.72,83.94 65.84,83.94 67.59,82.19 67.59,81.41 68.6,80.39 71.33,80.39 73.06,82.12 73.06,83.91 73.6,84.45 78.19,84.45 78.4,84.66 79.13,84.66 79.65,84.14 79.65,79.37 79.9,79.12 80.65,79.12 85.05,74.73 91.97,74.73 92.64,75.39 92.64,79.86 93.19,80.41 95.49,80.41 95.84,80.76 95.84,82.28 96.33,82.77 v1(96.33,82.85)
CNTR_TAP_CHA: length 7.1
  BOTTOM w0.381: v1(35.04,46.55) L29.2 C188.2 C187.1 ; v1(35.04,46.55) C190.1 C191.1 C187.1 ; v1(35.04,46.55) C187.1
CNTR_TAP_CHB: length 7.2
  BOTTOM w0.381: C199.1 v1(31.38,57.1) ; C199.1 C200.2 C194.1 31.38,58.03 v1(31.38,57.1) ; C199.1 30.3,56.21 ; v1(31.38,57.1) 31.38,56.2 ; C193.1 31.37,56.21 31.38,56.2 ; 31.38,56.2 L31.2
CNTR_TAP_CHC: length 7
  BOTTOM w0.381: v1(35.12,80.67) C206.1 ; v1(35.12,80.67) C209.1 C207.2 34.17,81.28 C206.1 ; v1(35.12,80.67) 34.77,80.06 L37.2 33.77,80.48 33.73,80.47 C206.1
CNTR_TAP_CHD: length 6.9
  BOTTOM w0.381: C218.1 C213.1 C212.1 v1(31.38,69.81) ; C218.1 C219.2 L39.2 v1(31.38,69.81) ; C218.1 v1(31.38,69.81)
CP1: length 31.8
  TOP w0.305: C222.1 97.46,94.56 v3(97.41,94.61) ; C222.1 98.04,94.56 v3(98.09,94.61) ; C222.1 96.82,94.62 95.81,95.63 95.81,101.88 94.46,103.23 94.46,106.48 101.63,113.64 106.76,113.64 v1(107.43,112.97) 107.89,112.51 v1(107.94,112.51)
  BOTTOM w0.305: U3.32 97.42,94.61 v3(97.41,94.61)
CP2: length 2.6
  TOP w0.254: C226.1 C225.1 106.27,94.77 105.41,94.77 v3(105.08,95.1)
D_IN1: length 19.5
  TOP w0.381: J20.1 60.82,123.67 arc(61.06,121.05) 61.81,118.52 R118.2 R115.1
D_IN2: length 20.2
  TOP w0.381: R347.1 R345.2 73.84,115.56 arc(74.55,120.22) 74.8,124.94 J21.1
DAC_ALT_SYNC_N: length 169.1
  L6_SIG w0.102: v2(208.92,64.14) 208.92,64.41 208.76,64.57 208.17,64.57 207.7,65.04 207.7,65.8 208.08,66.18 208.08,74.47 207.82,74.73 203.53,74.73 203.5,74.7 203.48,74.7 ; 65.15,68.33 64.97,68.33 64.96,68.32 58.23,68.32 57.97,68.06 57.97,66.99 57.93,66.95 57.93,66.94 57.55,66.56 v1(57.55,66.3)
  L6_SIG w0.127: 65.15,68.33 65.63,68.33 65.7,68.4 66.09,68.4 66.2,68.29 66.2,68.26 66.31,68.15 66.47,68.15 66.58,68.26 66.58,68.29 66.69,68.4 66.85,68.4 66.96,68.29 66.96,68.26 67.07,68.15 67.23,68.15 67.34,68.26 67.34,68.29 67.45,68.4 67.61,68.4 67.72,68.29 67.72,68.26 67.84,68.15 67.99,68.15 68.11,68.26 68.11,68.29 68.22,68.4 68.37,68.4 68.49,68.29 68.49,68.26 68.6,68.15 68.76,68.15 68.87,68.26 68.87,68.29 68.98,68.4 69.14,68.4 69.25,68.29 69.25,68.26 69.36,68.15 69.52,68.15 69.63,68.26 69.63,68.29 69.74,68.4 69.9,68.4 70.01,68.29 70.01,68.26 70.12,68.15 70.28,68.15 70.39,68.26 70.39,68.29 70.5,68.4 70.66,68.4 70.77,68.29 70.77,68.26 70.88,68.15 71.04,68.15 71.15,68.26 71.15,68.29 71.26,68.4 71.6,68.4 72.16,68.96 103.89,68.96 111,76.07 201.42,76.07 202.79,74.7 203.48,74.7
DAC_ALT_SYNC_P: length 169.1
  L6_SIG w0.102: 203.48,75.13 207.99,75.13 208.48,74.64 208.48,66.01 208.1,65.63 208.1,65.21 208.34,64.97 208.76,64.97 208.92,65.13 v2(208.92,65.41) ; 65.15,68.91 65.13,68.91 64.93,69.12 57.43,69.12 57.17,68.86 57.17,66.75 56.75,66.34 v1(56.75,66.3)
  L6_SIG w0.127: 65.15,68.91 65.63,68.91 65.7,68.83 71.42,68.83 71.98,69.39 103.71,69.39 110.82,76.5 201.6,76.5 202.97,75.13 203.48,75.13
DAC_SYNC_N: length 176.2
  L6_SIG w0.102: v1(57.55,60.7) 57.97,61.12 63.29,61.12 63.53,60.88 63.53,58.98 63.83,58.68 64.91,58.68 65.12,58.47 65.15,58.47 ; v2(208.92,75.56) 209.35,76 210.36,76 210.62,75.74 210.62,67.28 210.53,67.19 210.24,67.19 210.15,67.11 210.15,66.98 210.24,66.89 210.53,66.89 210.62,66.8 210.62,63.87 210.45,63.7 206.96,63.7 206.87,63.79 206.87,64.05 206.78,64.14 206.66,64.14 206.57,64.05 206.57,63.79 206.48,63.7 204.27,63.7 204.04,63.93 203.48,63.93
  L6_SIG w0.127: 65.15,58.47 66.43,58.47 66.8,58.1 66.95,58.1 66.99,58.14 67.15,58.14 67.26,58.02 67.26,57.87 67.22,57.83 67.22,57.68 68.7,56.2 72.25,56.2 73.31,57.25 76.58,57.25 77.6,58.27 77.6,59.06 78.87,60.32 192.94,60.32 193.05,60.44 193.05,60.56 193.16,60.67 193.32,60.67 193.43,60.56 193.43,60.44 193.55,60.32 195.86,60.32 198.91,63.37 201.88,63.37 202.44,63.93 203.48,63.93
DAC_SYNC_P: length 176.2
  L6_SIG w0.102: 203.48,63.5 203.64,63.5 203.67,63.53 203.88,63.53 204.1,63.3 210.62,63.3 211.02,63.7 211.02,75.91 210.53,76.4 209.35,76.4 v2(208.92,76.83) ; v1(56.75,60.7) 57.17,60.28 57.39,60.28 57.39,60.28 62.51,60.28 62.77,60.02 62.77,58.14 63.02,57.89 64.88,57.89 65.03,58.04 65.15,58.04
  L6_SIG w0.127: 65.15,58.04 66.25,58.04 68.52,55.77 72.43,55.77 73.48,56.82 76.76,56.82 78.03,58.09 78.03,58.88 79.05,59.89 196.04,59.89 199.09,62.94 202.06,62.94 202.62,63.5 203.48,63.5
DACCLK_IN: length 18.8
  BOTTOM w0.381: C4.1 16.97,62.88 arc(15.95,62.67) 15.08,62.1 10.85,57.86 arc(8.68,56.41) 6.12,55.91 J1.1
DACOUT: length 109.3
  TOP w0.127: R321.2 156.69,28.86 147.02,38.53 84.79,38.53 84.23,37.97 82.65,37.97 67.95,52.68 R21.2
DCLKOUT4N: length 4.4
  BOTTOM w0.203: C254.1 93.62,90.8 R188.1 94.4,90.64 94.98,90.64 95.36,91.02 97.19,91.02 97.28,91.11 U3.25
DCLKOUT4P: length 4.4
  BOTTOM w0.203: C253.1 93.62,90.14 R187.1 94.4,90.31 95.12,90.31 95.5,90.69 97.24,90.69 97.33,90.61 U3.24
DCLKOUT6N: length 3.7
  BOTTOM w0.203: U3.28 97.26,92.61 97.17,92.52 95.01,92.52 R289.1 94.83,92.67 C424.1
DCLKOUT6P: length 3.7
  BOTTOM w0.203: U3.27 97.28,92.11 97.19,92.19 95.01,92.19 R290.1 94.81,92.06 C423.1
DCLKOUT10N: length 4.1
  BOTTOM w0.203: U3.55 107.33,91.61 107.41,91.69 107.75,91.69 108.28,91.16 109.83,91.16 R293.1 110.64,90.96 C428.1
DCLKOUT10P: length 4.1
  BOTTOM w0.203: U3.54 107.31,92.11 107.39,92.02 107.89,92.02 108.42,91.49 109.91,91.49 R294.1 110.64,91.62 C427.1
DIN1: length 4
  TOP w0.381: C148.2 L16.2 64.74,101.1 63.98,98.24 T16.3
DIN1M: length 9.7
  TOP w0.203: C154.1 58.73,80.44 58.73,80.43 arc(58.6,80.2) 58.52,79.95 57.89,77.49 57.26,72.53 57.26,71.39 U1.Y10
DIN1P: length 9.7
  TOP w0.203: U1.Y11 56.93,71.28 56.93,72.56 57.56,77.55 58.24,80.2 C153.1
DIN2: length 3.9
  TOP w0.381: C495.2 L63.2 70.12,99.25 T18.3
DIN2M: length 9.7
  TOP w0.203: U1.Y7 59.76,71.29 59.76,71.45 arc(59.76,71.55) 59.76,71.65 59.84,72.88 arc(60.31,74.12) 60.96,75.26 60.97,75.28 arc(61.19,75.56) 61.42,75.84 arc(61.67,76.1) 61.94,76.34 63.51,77.64 arc(63.72,77.88) 63.84,78.18 63.84,78.18 63.98,78.73 arc(63.99,78.76) 64,78.8 arc(64.09,78.9) 64.22,78.95 C498.1
DIN2P: length 9.7
  TOP w0.203: C499.1 63.74,79.07 63.71,78.95 arc(63.68,78.88) 63.66,78.81 63.52,78.26 63.52,78.25 arc(63.44,78.05) 63.3,77.89 61.73,76.59 arc(61.44,76.34) 61.17,76.06 arc(60.93,75.77) 60.7,75.46 60.7,75.46 arc(60.06,74.37) 59.59,73.2 59.51,72.96 59.48,72.63 arc(59.44,72.07) 59.43,71.5 arc(59.43,71.48) 59.43,71.45 59.43,71.37 59.41,71.35 U1.Y8
DIV_IN: length 80
  L6_SIG w0.127: v3(90.55,104.27) 89.79,103.52 71.8,103.52 70.26,101.98 69.16,101.98 57.38,90.2 56.93,90.2 51.56,84.83 50.32,84.83 46.84,81.35 46.84,80.63 39.19,72.97 37.08,72.97 33.03,68.92 arc(32.72,68.45) 32.61,67.9 arc(32.54,67.54) 32.33,67.23 31.23,66.13 arc(31.01,65.81) 30.94,65.43 arc(31.02,65.02) 31.25,64.67 arc(31.82,64.29) 32.48,64.16 v1(33.43,64.16)
DM: length 5.3
  TOP w0.305: J33.2 192.44,119.29 192.26,119.11 192.26,118.68 193.6,117.34 193.6,116.46 R211.1
DP: length 5.3
  TOP w0.305: R212.1 193.17,116.48 193.17,117.16 191.83,118.5 191.83,119.11 191.64,119.29 J33.3
DP0_C2M_N: length 150.2
  BOTTOM w0.102: J32.C3 212.73,86.14 212.62,86.25 212.36,86.25 212.22,86.11 212.22,73.06 arc(212.16,72.78) 212,72.53 arc(211.73,72.35) 211.41,72.29 203.61,72.29 203.59,72.26 203.52,72.26 203.48,72.23
  BOTTOM w0.203: C37.1 77.29,73.56 96.39,73.56 97.73,72.23 203.48,72.23
DP0_C2M_P: length 150.2
  BOTTOM w0.102: 203.48,72.57 203.62,72.57 203.67,72.52 211.41,72.52 arc(211.64,72.56) 211.84,72.7 211.85,72.71 arc(211.95,72.87) 211.99,73.06 211.99,86.2 212.26,86.47 212.62,86.47 212.73,86.58 J32.C2
  BOTTOM w0.203: 203.48,72.57 203.47,72.56 97.86,72.56 96.53,73.89 77.29,73.89 C39.1
DP0_M2C_N: length 143.4
  TOP w0.152: 203.48,81.05 203.52,81.05 203.57,81.1 212.57,81.1 212.73,80.95 v1(212.73,80.64)
  TOP w0.203: 203.48,81.05 194.95,81.05 183.01,69.11 75.28,69.11 75.12,68.96 C35.1
DP0_M2C_P: length 143.5
  TOP w0.152: 203.48,81.38 212.57,81.38 212.73,81.53 v1(212.73,81.91)
  TOP w0.203: 203.48,81.38 194.81,81.38 182.87,69.44 75.28,69.44 75.12,69.6 C36.1
DP1_C2M_N: length 142.7
  BOTTOM w0.102: 203.48,60.76 203.53,60.81 215.16,60.81 215.27,60.71 J32.A23
  BOTTOM w0.203: 203.48,60.76 202.74,60.76 194.28,69.22 95.43,69.22 94.11,70.54 77.32,70.54 C33.1
DP1_C2M_P: length 142.7
  BOTTOM w0.102: 203.48,61.09 203.62,61.09 203.67,61.04 215.09,61.04 215.27,61.21 J32.A22
  BOTTOM w0.203: C34.1 77.27,70.87 94.24,70.87 95.56,69.55 194.42,69.55 202.88,61.09 203.48,61.09
DP1_M2C_N: length 146.8
  TOP w0.152: 203.48,83.62 203.52,83.62 203.54,83.64 211.78,83.64 214.38,86.23 215.1,86.23 215.27,86.07 v1(215.27,85.72)
  TOP w0.203: C38.1 75.12,72.01 75.28,72.16 181.58,72.16 193.04,83.62 203.48,83.62
DP1_M2C_P: length 146.8
  TOP w0.152: 203.48,83.95 203.52,83.95 203.54,83.92 211.67,83.92 214.26,86.51 215.11,86.51 215.27,86.66 v1(215.27,86.99)
  TOP w0.203: 203.48,83.95 192.9,83.95 181.45,72.49 75.28,72.49 75.12,72.64 C40.1
DP2_C2M_N: length 143.5
  BOTTOM w0.102: 203.48,55.78 203.51,55.78 203.52,55.77 215.12,55.77 215.27,55.62 J32.A27
  BOTTOM w0.203: 203.48,55.78 202.84,55.78 192.61,66.01 93.04,66.01 91.54,67.51 77.34,67.51 C31.1
DP2_C2M_P: length 143.5
  BOTTOM w0.102: 203.48,56.11 203.49,56.11 203.54,56.06 203.6,56.06 203.66,55.99 215.15,55.99 215.27,56.11 J32.A26
  BOTTOM w0.203: 203.48,56.11 202.98,56.11 192.75,66.34 93.18,66.34 91.68,67.84 77.24,67.84 C29.1
DP2_M2C_N: length 147.3
  TOP w0.152: v1(215.27,80.64) 215.27,80.99 215.11,81.14 214.87,81.14 212.31,78.57 203.48,78.57
  TOP w0.203: C32.1 74.88,66.07 183.42,66.07 195.93,78.57 203.48,78.57
DP2_M2C_P: length 147.3
  TOP w0.152: v1(215.27,81.91) 215.27,81.57 215.11,81.42 214.76,81.42 212.19,78.85 203.68,78.85 203.66,78.88 203.54,78.88 203.52,78.91 203.48,78.91
  TOP w0.203: C30.1 74.88,66.4 183.29,66.4 195.8,78.91 203.48,78.91
DP3_C2M_N: length 144.4
  BOTTOM w0.102: 203.48,50.58 203.58,50.58 203.64,50.63 204.13,50.63 204.19,50.69 215.16,50.69 215.27,50.59 J32.A31
  BOTTOM w0.203: C26.1 77.29,64.41 90.5,64.41 92,62.92 190.98,62.92 203.31,50.58 203.48,50.58
DP3_C2M_P: length 144.4
  BOTTOM w0.102: J32.A30 215.27,51.03 215.16,50.92 204.09,50.92 204.04,50.86 203.54,50.86 203.49,50.91 203.48,50.91
  BOTTOM w0.203: 203.48,50.91 203.45,50.91 191.11,63.25 92.14,63.25 90.64,64.74 77.29,64.74 C25.1
DP3_M2C_N: length 146.4
  TOP w0.152: 203.48,76.03 203.52,76.03 203.54,76.06 215.11,76.06 215.27,75.91 v1(215.27,75.56)
  TOP w0.203: C27.1 74.83,62.97 184.35,62.97 197.42,76.03 203.48,76.03
DP3_M2C_P: length 146.5
  TOP w0.152: v1(215.27,76.83) 215.27,76.49 215.11,76.34 203.54,76.34 203.52,76.37 203.48,76.37
  TOP w0.203: 203.48,76.37 197.28,76.37 184.22,63.3 74.93,63.3 C28.1
DP4_C2M_N: length 144
  BOTTOM w0.102: 203.48,45.55 203.62,45.55 203.67,45.61 215.02,45.61 215.16,45.61 215.27,45.5 J32.A35
  BOTTOM w0.203: 203.48,45.55 199.35,45.55 188.14,56.77 87.6,56.77 86.06,58.32 77.29,58.32 C19.1
DP4_C2M_P: length 144
  BOTTOM w0.102: J32.A34 215.27,45.94 215.16,45.83 214.92,45.83 203.53,45.83 203.48,45.88
  BOTTOM w0.203: C17.1 77.29,58.65 86.19,58.65 87.74,57.1 188.27,57.1 199.49,45.88 203.48,45.88
DP4_M2C_N: length 146.8
  TOP w0.152: v1(215.27,70.48) 215.27,70.8 215.11,70.95 203.48,70.95
  TOP w0.203: C20.1 74.88,56.92 171.04,56.92 171.07,56.95 185.86,56.95 199.86,70.95 203.48,70.95
DP4_M2C_P: length 146.8
  TOP w0.152: v1(215.27,71.75) 215.27,71.44 215.11,71.29 203.48,71.29
  TOP w0.203: 203.48,71.29 199.72,71.29 185.72,57.28 170.93,57.28 170.9,57.25 74.88,57.25 C18.1
DP5_C2M_N: length 143.6
  BOTTOM w0.102: v2(215.27,40) 215.27,40.42 215.16,40.53 203.56,40.53 203.5,40.47 203.48,40.47
  BOTTOM w0.203: C10.1 77.29,52.35 79.32,52.35 80.85,50.83 188.19,50.83 198.54,40.47 203.48,40.47
DP5_C2M_P: length 143.6
  BOTTOM w0.102: v2(215.27,41.27) 215.27,40.86 215.16,40.75 203.56,40.75 203.5,40.81 203.48,40.81
  BOTTOM w0.203: 203.48,40.81 198.68,40.81 188.33,51.16 80.99,51.16 79.46,52.68 77.29,52.68 C9.1
DP5_M2C_N: length 147.2
  TOP w0.152: v1(215.27,65.41) 215.27,65.66 215.02,65.9 203.54,65.9 203.52,65.87 203.48,65.87
  TOP w0.203: C13.1 74.88,50.83 186.87,50.83 201.92,65.87 203.48,65.87
DP5_M2C_P: length 147.2
  TOP w0.152: v1(215.27,66.67) 215.27,66.37 215.07,66.18 203.54,66.18 203.52,66.21 203.48,66.21
  TOP w0.203: C14.1 74.88,51.16 186.73,51.16 201.78,66.21 203.48,66.21
DP6_C2M_N: length 142.5
  BOTTOM w0.102: 203.48,43.01 203.5,43.01 203.56,43.07 213.89,43.07 214,42.96 J32.B37
  BOTTOM w0.203: C11.1 77.27,55.24 82.7,55.24 84.18,53.77 188.39,53.77 199.15,43.01 203.48,43.01
DP6_C2M_P: length 142.5
  BOTTOM w0.102: J32.B36 214,43.4 213.89,43.29 203.56,43.29 203.5,43.35 203.48,43.35
  BOTTOM w0.203: 203.48,43.35 199.28,43.35 188.53,54.1 84.31,54.1 82.84,55.58 77.32,55.58 C12.1
DP6_M2C_N: length 145.8
  TOP w0.152: 203.48,68.41 203.52,68.41 203.54,68.44 213.84,68.44 214,68.29 v2(214,67.94)
  TOP w0.203: 203.48,68.41 200.77,68.41 186.23,53.87 75.28,53.87 75.12,53.72 C15.1
DP6_M2C_P: length 145.8
  TOP w0.152: v2(214,69.22) 214,68.87 213.84,68.72 203.54,68.72 203.52,68.75 203.48,68.75
  TOP w0.203: 203.48,68.75 200.64,68.75 186.1,54.2 75.28,54.2 75.12,54.36 C16.1
DP7_C2M_N: length 142.9
  BOTTOM w0.102: J32.B33 214,48.03 213.89,48.13 203.62,48.13 203.58,48.09 203.5,48.09 ; 203.5,48.09 203.48,48.09 ; 203.5,48.09 203.49,48.08 203.48,48.08
  BOTTOM w0.203: 203.48,48.08 200.28,48.08 188.29,60.07 89.08,60.07 87.78,61.37 77.29,61.37 C23.1
DP7_C2M_P: length 142.9
  BOTTOM w0.102: J32.B32 214,48.48 213.88,48.36 203.67,48.36 203.62,48.41 203.48,48.41
  BOTTOM w0.203: C21.1 77.29,61.7 87.92,61.7 89.21,60.4 188.43,60.4 200.42,48.41 203.48,48.41
DP7_M2C_N: length 145.3
  TOP w0.152: v2(214,73.02) 214,73.34 213.84,73.49 203.48,73.49
  TOP w0.203: C24.1 74.83,59.94 184.96,59.94 198.51,73.49 203.48,73.49
DP7_M2C_P: length 145.4
  TOP w0.152: 203.48,73.84 203.49,73.83 213.8,73.83 214,74.02 v2(214,74.3)
  TOP w0.203: C22.1 74.88,60.27 184.83,60.27 198.38,73.83 203.45,73.83 203.47,73.84 203.48,73.84
EE_ADDR0_RX: length 49.6
  TOP w0.127: U31.1 192.71,20.17 191.08,21.79 191.08,27.81 188.77,30.12 188.77,37.82 197.87,46.91 212.12,46.91 212.67,46.35 v2(212.73,46.35)
EE_ADDR1_RX: length 45.9
  TOP w0.127: v2(211.46,45.08) 210.77,45.77 197.43,45.77 189.23,37.57 189.23,30.45 191.57,28.12 191.57,22.53 192.66,21.44 U31.2
EEDATA: length 4
  TOP w0.127: U5.61 187.31,99.85 187.18,99.72 ; 187.18,99.72 v1(186.51,100.38) ; 187.18,99.72 U8.3
FBBANDSEL1: length 147.7
  L6_SIG w0.102: 65.15,63.52 60.63,63.52 60.37,63.26 60.37,62.98 60.11,62.72 59.83,62.72 59.57,62.46 59.57,62.18 59.31,61.92 58.95,61.92 58.53,61.5 v1(58.35,61.5)
  L6_SIG w0.127: 65.15,63.52 65.47,63.84 67.55,63.84 67.73,64.02 70.36,64.02 70.97,63.41 78.89,63.41 78.91,63.39 105.5,63.39 107.35,65.24 107.35,65.54 107.61,65.8 107.91,65.8 109.23,67.12 109.23,67.29 109.49,67.55 109.66,67.55 109.93,67.82 151.99,67.82 153.11,68.94 157.37,68.94 157.86,68.45 157.86,68.22 v1(158.32,67.77)
  L8_PWR_SIG w0.127: v1(158.32,67.77) 158.74,68.19 158.74,68.59 159.04,68.89 159.04,71.01 158.74,71.32 158.74,72.43 159.42,73.11 159.42,73.95 159,74.37 159,82.05 159.22,82.26 159.22,82.63 159,82.85 159,89.67 159.19,89.86 159.19,90.23 159,90.42 159,92 157.43,93.57 157.43,100.89 156.96,101.36 156.96,103.8 157.27,104.11 157.27,106.42 J9.50
FBBANDSEL2: length 136.4
  TOP w0.102: U1.N9 58.75,65.9 58.75,67.23 58.99,67.47 59.31,67.47 59.58,67.74 59.58,68.06 59.79,68.27 60.11,68.27 60.38,68.54 60.38,69.66 60.65,69.93 60.91,69.93 61.15,70.17 61.15,71.26 61.38,71.49 62.94,71.49 62.96,71.5
  TOP w0.127: v1(122.43,84.81) 122.83,85.22 129.44,85.22 130.15,85.93 130.15,86.46 131.09,87.4 131.57,87.4 132.54,88.37 132.54,91.95 134.25,93.66 134.25,106.51 v1(134.32,106.58) ; v1(89,82.27) 87.91,81.18 76.71,81.18 72.77,77.24 66.36,77.24 64.43,75.31 64.43,72.43 63.52,71.52 62.98,71.52 62.96,71.5
  L4_SIG w0.127: v1(134.32,106.58) 138.51,106.58 139.97,108.04 139.97,108.32 140.87,109.22 159.87,109.22 J9.53 ; v1(122.43,84.81) 119.75,82.13 98.62,82.13 97.75,81.27 95.83,81.27 95.49,81.61 89.66,81.61 v1(89,82.27)
FMC_FSPICLKA: length 90.8
  L6_SIG w0.102: 203.48,87.63 205.33,87.63 205.87,87.1 205.87,82.68 v2(205.11,81.91)
  L6_SIG w0.127: v1(179.25,89.28) 179.25,88.82 180.05,88.02 180.55,88.02 180.71,88.19 197.18,88.19 198.12,87.25 202.46,87.25 202.84,87.63 203.48,87.63
  L8_PWR_SIG w0.127: v1(179.25,89.28) 178.51,90.02 178.51,104.11 177.86,104.76 177.86,113.75 171.5,120.12 158.45,120.12 156.91,118.58 156.22,118.58 155.66,118.02 155.66,117.34 154.37,116.04 153.68,116.04 153.12,115.48 153.12,114.8 v1(151.97,113.64)
FMC_FSPICLKB: length 87.3
  L6_SIG w0.102: v2(205.11,80.64) 204.29,79.83 203.48,79.83
  L6_SIG w0.127: v1(176.4,79.83) 177.14,80.57 202.74,80.57 203.48,79.83
  L8_PWR_SIG w0.127: v1(176.4,79.83) 176.4,90.2 175.82,90.78 175.82,98.76 176.11,99.04 176.11,104.26 173.38,106.98 173.38,110.6 172.74,111.24 172.74,116.21 170.15,118.8 161.52,118.8 160.74,118.02 160.74,117.67 159.12,116.04 158.76,116.04 158.2,115.48 158.2,114.85 v1(157.02,113.66)
FMC_FSPICLKC: length 82.3
  L4_SIG w0.102: v2(205.11,78.11) 204.65,78.56 203.48,78.56
  L4_SIG w0.127: 203.48,78.56 202.95,78.56 201.04,80.47 172.47,80.47 v1(171.98,79.98)
  L8_PWR_SIG w0.127: v1(162.33,113.69) 163.03,114.39 163.03,115.23 163.84,116.04 164.91,116.04 165.33,115.62 165.96,115.62 166.38,116.04 170.4,116.04 171.7,114.73 171.7,110.64 171.47,110.41 171.47,107.52 172.17,106.82 172.17,103.16 173.45,101.88 173.45,99.29 172.15,97.98 172.15,80.15 v1(171.98,79.98)
FMC_FSPICLKD: length 76.8
  L6_SIG w0.102: v2(205.11,76.83) 204.67,76.4 203.48,76.4
  L6_SIG w0.127: 203.48,76.4 202.9,76.4 201.45,77.85 171.35,77.85 v1(171.25,77.75)
  L8_PWR_SIG w0.127: v1(171.25,77.75) 171.25,80.54 171.64,80.94 171.64,89.62 171.09,90.17 171.09,98.07 173.02,100 173.02,101.65 171.77,102.9 171.77,106.1 171.04,106.83 171.04,113.49 170.4,114.13 167.6,114.13 v1(167.16,113.69)
FMC_FSPIDA: length 95.8
  L6_SIG w0.102: 203.48,73.85 204.66,73.85 v2(205.11,74.3)
  L6_SIG w0.127: v1(177.39,74.9) 177.52,74.78 180.37,74.78 180.38,74.79 180.75,74.79 180.77,74.78 182.23,74.78 182.31,74.87 182.68,74.87 182.77,74.78 192.49,74.78 192.5,74.79 198.08,74.79 198.09,74.78 200.41,74.78 201.33,73.85 203.48,73.85
  L8_PWR_SIG w0.127: v1(177.39,74.9) 177.76,75.27 177.76,81.96 177.27,82.45 177.27,86.9 177.72,87.36 177.72,92.05 177.48,92.29 177.48,99.78 177.67,99.97 177.67,104.17 177.15,104.68 177.15,111.56 176.84,111.88 176.84,113 170.35,119.49 160.28,119.49 159.37,118.58 158.76,118.58 158.2,118.02 158.2,117.41 156.83,116.04 156.22,116.04 155.66,115.48 155.66,114.87 v1(154.46,113.66)
FMC_FSPIDB: length 86.4
  L6_SIG w0.102: v2(205.11,73.02) 204.67,73.46 203.66,73.46 203.55,73.36 203.48,73.36
  L6_SIG w0.127: 203.48,73.36 201.17,73.36 200.76,73.77 176.45,73.77 175.9,73.22 175.2,73.22 174.57,73.84 v1(166.66,73.84)
  L8_PWR_SIG w0.127: v1(166.66,73.84) 166.66,80.66 167.4,81.39 167.4,91.73 167.16,91.97 167.16,97.97 167.41,98.22 167.41,108.47 167.28,108.6 167.28,108.6 167.02,108.86 167.02,109.23 167.28,109.49 167.28,109.49 167.41,109.61 167.41,111.28 166.6,112.09 163.54,112.09 162.45,113.18 160.25,113.18 159.74,113.69 v1(159.64,113.69)
FMC_FSPIDC: length 83.6
  L6_SIG w0.102: v2(205.11,70.48) 204.67,70.05 203.48,70.05
  L6_SIG w0.127: 203.48,70.05 197.35,70.05 197.34,70.04 186.39,70.04 186.38,70.05 172.49,70.05 171.31,71.23 170.35,71.23 v1(169.95,70.84)
  L8_PWR_SIG w0.127: v1(169.95,70.84) 169.85,70.94 169.85,73.2 168.95,74.1 168.95,83.48 169.94,84.47 169.94,94.25 169.61,94.58 169.61,95.31 169.85,95.55 169.85,107.78 169.84,107.79 169.84,108.41 169.85,108.43 169.85,110.97 167.84,112.98 165.33,112.98 v1(164.62,113.69)
FMC_FSPIDD: length 79.2
  L6_SIG w0.102: v2(205.11,69.22) 203.48,69.22
  L6_SIG w0.127: 203.48,69.22 172.36,69.22 170.79,70.79 v1(170.69,70.79)
  L8_PWR_SIG w0.127: v1(169.7,113.69) 169.7,113.31 170.45,112.56 170.45,108.59 170.14,108.29 170.14,107.92 170.45,107.61 170.45,101.75 170.62,101.57 170.62,82.05 170.35,81.78 170.35,74.07 171.06,73.36 171.06,72.99 170.69,72.62 v1(170.69,70.79)
FMC_LMK_CS: length 50.9
  TOP w0.127: U33.5 v1(175.65,89.8)
  L4_SIG w0.102: 206.35,67.94 205.76,67.94 204.67,69.04 203.68,69.04
  L4_SIG w0.127: v1(175.72,73.66) 185.3,73.66 185.31,73.67 198.39,73.67 203.02,69.04 203.68,69.04 ; v2(206.38,67.94) 206.35,67.94
  L8_PWR_SIG w0.127: v1(175.65,89.8) 175.72,89.74 175.72,89.53 175.87,89.38 175.87,73.81 v1(175.72,73.66)
FMC_LMK_SCK: length 53.7
  TOP w0.127: U33.2 v1(173.7,90.15)
  L4_SIG w0.127: v1(173.84,75.13) 175.01,76.3 199.01,76.3 202.77,72.54 203.49,72.54 203.5,72.56 204.17,72.56 204.18,72.54 205.69,72.54 207.16,71.07 207.16,71.02 207.65,70.54 v2(207.65,70.48)
  L8_PWR_SIG w0.127: v1(173.84,75.13) 172.97,76 172.97,89.43 v1(173.7,90.15)
FMC_LMK_SDIO: length 54.5
  TOP w0.127: U33.3 v1(174.35,89.76)
  L4_SIG w0.102: v2(207.65,69.22) 207.65,69.87 207.21,70.31 207.21,70.43 206.39,71.26 203.63,71.26 203.48,71.41
  L4_SIG w0.127: 203.48,71.41 202.88,72.01 201.75,72.01 197.92,75.84 175.54,75.84 v1(174.4,74.7)
  L8_PWR_SIG w0.127: v1(174.35,89.76) 173.57,88.98 173.57,81.9 174.02,81.46 174.02,78.2 174.69,77.53 174.69,74.99 v1(174.4,74.7)
FMC_LMK_SDO: length 51.8
  TOP w0.127: U33.4 v1(175,90.2)
  L4_SIG w0.102: v2(206.38,69.22) 205.71,69.88 203.48,69.88
  L4_SIG w0.127: v1(175.06,74.19) 179.6,74.19 180.28,74.87 198.08,74.87 203.07,69.88 203.48,69.88
  L8_PWR_SIG w0.127: v1(175.06,74.19) 175.21,74.35 175.21,78.41 174.82,78.8 174.82,81.04 174.96,81.18 174.96,88.5 175.45,89 175.45,89.36 175.19,89.62 175.18,89.62 175.06,89.75 175.06,90.14 v1(175,90.2)
FMC_RXADSA1PD: length 85.2
  L8_PWR_SIG w0.102: v2(203.84,80.64) 203.48,81
  L8_PWR_SIG w0.127: 203.48,81 195.28,89.2 180.44,89.2 178.23,86.99 v1(178.23,86.51)
  BOTTOM w0.127: v1(178.23,86.51) 178.23,88.06 169.53,96.76 135.85,96.76 134.49,98.12 134.49,98.5 133.55,99.44 132.03,99.44 130.63,100.84 J7.9
FMC_RXADSA2PD: length 81.1
  L8_PWR_SIG w0.102: 203.48,79.73 v2(203.84,79.38)
  L8_PWR_SIG w0.127: v1(181.05,87.71) 181.05,87.96 181.79,88.7 193.78,88.7 202.74,79.73 203.48,79.73
  BOTTOM w0.127: v1(181.05,87.71) 179.09,87.71 172.54,94.26 172.54,94.69 170,97.23 137.69,97.23 136.83,98.09 136.83,98.68 135.99,99.52 134.52,99.52 J7.12
FMC_RXADSAFAST: length 127.7
  TOP w0.127: v1(159.87,105.84) 159.87,97.92 159.51,97.56 159.51,96.19 159.52,96.18 159.52,86.33 159.5,86.31 159.5,78.91 v1(164.16,74.24)
  L4_SIG w0.102: v1(207.65,66.67) 207.65,66.6 207.14,66.09 203.48,66.09
  L4_SIG w0.127: v1(164.16,74.24) 164.16,74.68 165.21,75.73 167.06,75.73 167.55,75.24 167.55,75.06 171.7,70.91 171.7,70.61 172.31,70 198.76,70 202.67,66.09 203.48,66.09
  BOTTOM w0.127: v1(159.87,105.84) 159.22,106.49 143.29,106.49 142.8,105.99 141.58,105.99 141.28,106.3 134.72,106.3 134.47,106.05 134.09,106.05 133.32,106.81 120.27,106.81 119.38,107.7 119.38,109.12 118.11,110.39 J9.3
FMC_RXAPD2H: length 74.4
  L3_PWR w0.102: v2(203.84,76.83) 204.32,77.32 204.32,88.65
  L3_PWR w0.127: v1(199.66,95.01) 199.66,94.12 204.32,89.46 204.32,88.65
  L4_SIG w0.127: J7.33 150.98,100.86 151.99,99.85 151.99,98.12 153.34,96.77 170.69,96.77 172.02,98.11 177.3,98.11 177.88,97.54 177.88,96.96 179.34,95.49 180.68,95.49 180.97,95.78 193.7,95.78 194.76,94.72 199.37,94.72 v1(199.66,95.01)
FMC_RXAPD2L: length 75.3
  L3_PWR w0.102: v2(203.84,75.56) 204.45,75.56 205.54,76.66 205.54,88.65
  L3_PWR w0.127: 205.54,88.65 205.54,89.05 200.2,94.39 200.2,96.62 v1(199.95,96.88)
  L4_SIG w0.127: J7.36 153.49,99.75 155.08,98.16 155.08,97.93 155.73,97.28 170.38,97.28 171.65,98.55 177.62,98.55 179.76,96.42 191.91,96.42 192.22,96.11 193.01,96.11 193.54,96.64 199.71,96.64 v1(199.95,96.88)
FMC_RXBDSA1PD: length 80.4
  L8_PWR_SIG w0.102: v2(203.84,73.02) 203.48,73.38 203.48,73.93
  L8_PWR_SIG w0.127: 203.48,73.93 189.22,88.19 182.58,88.19 v1(182.12,87.73)
  BOTTOM w0.127: v1(182.12,87.73) 173.75,96.1 172.83,96.1 169.6,99.34 137.24,99.34 J7.15
FMC_RXBDSA2PD: length 78.4
  L8_PWR_SIG w0.102: 203.48,72.11 v2(203.84,71.75)
  L8_PWR_SIG w0.127: v1(183.11,87.71) 183.77,87.05 188.95,87.05 193.34,82.65 193.34,82 203.23,72.11 203.48,72.11
  BOTTOM w0.127: v1(183.11,87.71) 182.92,87.71 174.35,96.28 174.35,96.99 173.16,98.17 172.19,98.17 170.48,99.87 139.62,99.87 138.63,100.86 J7.18
FMC_RXBDSAFAST: length 121.8
  TOP w0.127: v1(149.61,107.16) 149.99,106.78 149.99,104.88 150.51,104.36 151.09,104.36 151.38,104.06 151.38,103.25 150,101.87 150,92.72 150.42,92.3 150.42,85.27 v1(161.42,74.27)
  L4_SIG w0.102: v1(207.65,62.86) 207.01,63.5 203.48,63.5
  L4_SIG w0.127: v1(161.42,74.27) 161.42,73.61 162.66,72.36 165.94,72.36 168.91,69.39 197.54,69.39 203.43,63.5 203.48,63.5
  BOTTOM w0.127: v1(149.61,107.16) 149.3,107.09 149.1,106.88 142.23,106.88 142.14,106.97 141.78,106.97 141.69,106.88 137.87,106.88 137.26,107.49 137.26,108.28 136.74,108.8 132.9,108.8 132.74,108.64 131.75,108.64 131.18,109.21 121.78,109.21 J9.6
FMC_RXBPD2H: length 82.2
  L3_PWR w0.102: 203.48,68.3 v2(205.11,66.67)
  L3_PWR w0.127: 203.48,68.3 203.17,68.61 203.17,89.84 199.03,93.98 199.03,100.94 v1(199.21,101.12)
  L4_SIG w0.127: J7.39 157.21,99.68 159.55,99.68 159.65,99.58 162.47,99.58 162.61,99.44 177.04,99.44 177.6,100 183.92,100 184.35,99.57 187.17,99.57 187.6,99.14 192.61,99.14 194.59,101.12 v1(199.21,101.12)
FMC_RXBPD2L: length 80.9
  L3_PWR w0.102: 203.48,66.01 204.09,65.41 v2(205.11,65.41)
  L3_PWR w0.127: v1(198.55,101.78) 198.55,93.6 202.46,89.69 202.46,67.03 203.48,66.01
  L4_SIG w0.127: J7.42 159.76,100.86 160.72,99.91 168.34,99.91 168.43,99.82 176.63,99.82 177.7,100.89 193.22,100.89 194.11,101.78 v1(198.55,101.78)
FMC_RXDSASW: length 87.8
  L6_SIG w0.127: v1(196.39,113.51) 195.55,113.51 194.91,112.86 182.41,112.86 181.96,112.41 181.67,112.41 181.39,112.69 173.06,112.69 171.73,111.35 157.2,111.35 156.24,110.39 J9.48
  L8_PWR_SIG w0.102: 208.38,73.58 208.92,73.05 v2(208.92,73.02)
  L8_PWR_SIG w0.127: v1(196.39,113.51) 196.37,113.51 195.96,113.11 195.96,102.87 198.65,100.18 198.65,95.38 205.82,88.21 205.82,76.75 208.38,74.19 208.38,73.58
